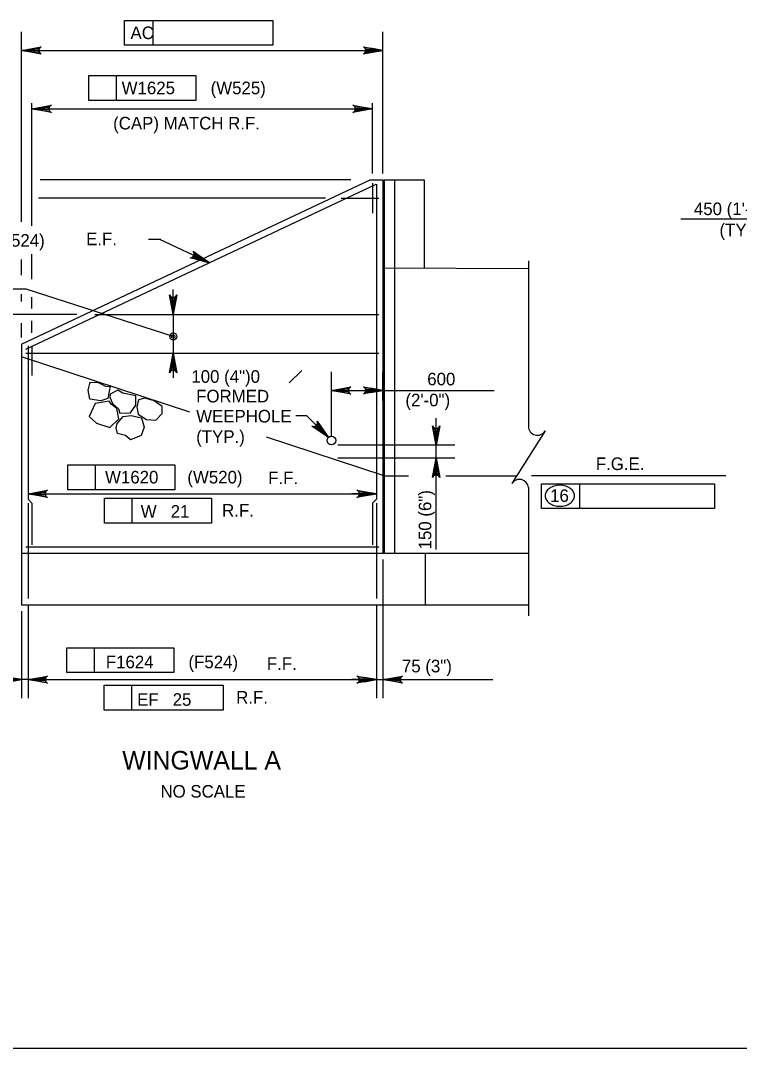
# Model space of a CAD drawing. Extents: x 638340 to 640241, y 295465 to 298435.
# Drawn here: x 638624.2 to 638795.5, y 296074.5 to 296319.4 of the extents above; entities that cross this region are included whole.
import ezdxf

# ---------------------------------------------------------------- set-up
doc = ezdxf.new("R2010")
doc.units = 0
for name, color, linetype in [('10', 7, 'Continuous'), ('2', 7, 'Continuous'), ('3', 7, 'Continuous'), ('4', 7, 'Continuous'), ('5', 7, 'Continuous'), ('6', 7, 'Continuous')]:
    doc.layers.add(name, color=color, linetype=linetype)

# ---------------------------------------------------------------- blocks, each defined once
blk = doc.blocks.new('ROCK')
at = {"layer": '4'}
for points in [[(2.36725, 1.088), (2.2065, 0.82625), (2.378625, 0.506625), (2.66975, 0.3095), (3.128875, 0.403375), (3.48475, 0.6775), (3.4915, 1.123375), (3.25625, 1.36725), (2.783625, 1.308375)], [(1.10175, -0.02725), (1.4015, -0.159125), (1.78825, -0.148875), (1.980875, -0.266), (2.343375, 0.09475), (2.27875, 0.5505), (1.969375, 0.883), (1.4225, 0.553625), (1.152875, 0.479), (1.0105, 0.082)], [(0.74675, 0.359875), (0.882, 0.16), (1.072875, -0.144), (0.892, -0.457375), (0.448125, -0.758625), (0.1, -0.49325), (-0.095, -0.146375), (0.202875, 0.1025), (0.579125, 0.219875)], [(2.231375, -0.71725), (2.2025, -0.266375), (2.45475, 0.037125), (2.9085, 0.28875), (3.2995, 0.047625), (3.46875, -0.344), (3.231625, -0.855), (2.92, -0.860375), (2.5765, -1.054625), (2.340375, -0.904375)], [(1.2085, -0.192875), (0.778375, -0.737625), (1.008375, -1.391375), (1.48725, -1.396875), (2.09825, -1.106625), (2.133375, -0.486375), (1.723125, -0.203375), (1.37425, -0.239875)]]:
    blk.add_lwpolyline(points, close=True, dxfattribs=at)

msp = doc.modelspace()

# ---------------------------------------------------------------- linework, layer by layer
at = {"layer": '10'}
for p, q in [((638624.42, 296242.32), (638707.47, 296281.44)), ((638707.47, 296281.44), (638710.54, 296281.44)), ((638710.54, 296281.44), (638710.54, 296192.49)), ((638710.8, 296281.44), (638720.35, 296281.44)), ((638710.8, 296281.44), (638710.8, 296192.49)), ((638713.27, 296281.44), (638713.27, 296192.49)), ((638720.35, 296281.44), (638720.35, 296260.47)), ((638710.8, 296260.51), (638745.21, 296260.36)), ((638624.42, 296242.32), (638624.42, 296180.18)), ((638664.51, 296226.11), (638624.42, 296239.24)), ((638710.8, 296210.94), (638682.76, 296220.13)), ((638710.8, 296210.94), (638716.64, 296210.94)), ((638725.5, 296210.94), (638742.46, 296210.94)), ((638624.42, 296192.49), (638745.21, 296192.49)), ((638720.6, 296192.49), (638720.6, 296180.18)), ((638624.42, 296180.18), (638745.21, 296180.18))]:
    msp.add_line(p, q, dxfattribs=at)
at = {"layer": '2'}
msp.add_line((639261.46, 296074.46), (638475.46, 296074.46), dxfattribs=at)
at = {"layer": '3'}
for p, q in [((638815.71, 296272.08), (638781.51, 296272.08)), ((638745.21, 296262.18), (638745.21, 296222.71)), ((638625.48, 296255.4), (638588.19, 296255.4)), ((638660.55, 296244.13), (638625.48, 296255.4)), ((638749.19, 296221.64), (638741.29, 296209.07)), ((638745.21, 296208.14), (638745.21, 296177.56))]:
    msp.add_line(p, q, dxfattribs=at)
for radius in [0.833, 0.417]:
    msp.add_circle((638660.55, 296244.13), radius, dxfattribs=at)
for centre, start, end in [((638747.34, 296222.71), 180, 330), ((638743.09, 296207.94), 5.3286, 147.8672)]:
    msp.add_arc(centre, 2.13, start, end, dxfattribs=at)
at = {"layer": '4'}
for p, q in [((638648.96, 296319.41), (638684.26, 296319.41)), ((638648.96, 296313.51), (638648.96, 296319.41)), ((638655.8, 296313.51), (638655.8, 296319.41)), ((638684.26, 296319.41), (638684.26, 296313.51)), ((638624.42, 296271.46), (638624.42, 296316.74)), ((638710.54, 296282.98), (638710.54, 296316.74)), ((638627.37, 296312.31), (638707.59, 296312.31)), ((638684.26, 296313.51), (638648.96, 296313.51)), ((638640.43, 296306.28), (638665.97, 296306.28)), ((638640.43, 296300.38), (638640.43, 296306.28)), ((638647.03, 296300.38), (638647.03, 296306.28)), ((638665.97, 296306.28), (638665.97, 296300.38)), ((638626.85, 296270.51), (638626.85, 296299.7)), ((638665.97, 296300.38), (638640.43, 296300.38)), ((638708.02, 296282.98), (638708.02, 296299.7)), ((638626.85, 296298.39), (638708.02, 296298.39)), ((638702.87, 296281.44), (638628.84, 296281.44)), ((638696.87, 296277.07), (638628.45, 296277.07)), ((638657.58, 296267.21), (638654.63, 296267.21)), ((638669.16, 296261.69), (638657.39, 296267.21)), ((638624.42, 296258.7), (638624.42, 296262.48)), ((638626.85, 296257.75), (638626.85, 296263.74)), ((638660.55, 296252.34), (638660.55, 296255.3)), ((638624.42, 296252.49), (638624.42, 296254.18)), ((638626.85, 296250.79), (638626.85, 296253.5)), ((638637.55, 296249.39), (638621.53, 296249.39)), ((638626.85, 296244.99), (638626.85, 296247.89)), ((638660.55, 296249.39), (638660.55, 296240.16)), ((638624.42, 296243.85), (638624.42, 296247.27)), ((638660.55, 296237.21), (638660.55, 296234.26)), ((638688.2, 296233.05), (638691.19, 296236.04)), ((638698.24, 296220.34), (638698.24, 296235.72)), ((638710.54, 296228.75), (638710.54, 296235.72)), ((638701.19, 296231.29), (638737.05, 296231.29)), ((638692.39, 296225.25), (638689.75, 296225.25)), ((638697.52, 296220.05), (638692.39, 296225.25)), ((638723.22, 296193.38), (638723.22, 296224.68)), ((638699.78, 296218.29), (638727.65, 296218.29)), ((638635.42, 296213.52), (638660.96, 296213.52)), ((638635.42, 296207.61), (638635.42, 296213.52)), ((638642.02, 296207.61), (638642.02, 296213.52)), ((638660.96, 296213.52), (638660.96, 296207.61)), ((638699.78, 296215.21), (638727.65, 296215.21)), ((638792.29, 296210.94), (638745.96, 296210.94)), ((638748.33, 296209.01), (638789.54, 296209.01)), ((638748.33, 296203.1), (638748.33, 296209.01)), ((638757.5, 296203.1), (638757.5, 296209.01)), ((638789.54, 296209.01), (638789.54, 296203.1)), ((638625.96, 296206.65), (638709.01, 296206.65)), ((638631.37, 296206.65), (638634.33, 296206.65)), ((638660.96, 296207.61), (638635.42, 296207.61)), ((638706.05, 296206.65), (638703.1, 296206.65)), ((638644.16, 296205.58), (638669.7, 296205.58)), ((638644.16, 296199.67), (638644.16, 296205.58)), ((638650.75, 296199.67), (638650.75, 296205.58)), ((638669.7, 296205.58), (638669.7, 296199.67)), ((638789.54, 296203.1), (638748.33, 296203.1)), ((638669.7, 296199.67), (638644.16, 296199.67)), ((638710.54, 296190.95), (638710.54, 296157.91)), ((638625.96, 296180.18), (638625.96, 296157.91)), ((638709.01, 296180.18), (638709.01, 296157.91)), ((638624.42, 296178.65), (638624.42, 296157.91)), ((638635.16, 296169.93), (638660.7, 296169.93)), ((638635.16, 296164.03), (638635.16, 296169.93)), ((638641.76, 296164.03), (638641.76, 296169.93)), ((638660.7, 296169.93), (638660.7, 296164.03)), ((638625.96, 296162.34), (638624.42, 296162.34)), ((638628.91, 296162.34), (638706.05, 296162.34)), ((638631.58, 296162.34), (638634.53, 296162.34)), ((638660.7, 296164.03), (638635.16, 296164.03)), ((638706.05, 296162.34), (638703.1, 296162.34)), ((638709.01, 296162.34), (638710.54, 296162.34)), ((638713.5, 296162.34), (638716.45, 296162.34)), ((638716.45, 296162.34), (638736.72, 296162.34)), ((638644.06, 296160.99), (638672.48, 296160.99)), ((638644.06, 296155.09), (638644.06, 296160.99)), ((638650.65, 296155.09), (638650.65, 296160.99)), ((638672.48, 296160.99), (638672.48, 296155.09)), ((638672.48, 296155.09), (638644.06, 296155.09))]:
    msp.add_line(p, q, dxfattribs=at)
for points in [[(638624.42, 296312.31), (638629.08, 296313.19), (638628.72, 296312.94), (638628.54, 296312.63), (638628.48, 296312.31), (638628.54, 296312), (638628.72, 296311.69), (638629.08, 296311.44), (638624.42, 296312.31), (638628.72, 296311.69), (638628.54, 296312), (638624.42, 296312.31), (638628.48, 296312.31), (638628.54, 296312.63), (638624.42, 296312.31), (638628.72, 296312.94)], [(638710.54, 296312.31), (638705.88, 296311.44), (638706.24, 296311.69), (638706.43, 296312), (638706.48, 296312.31), (638706.43, 296312.63), (638706.24, 296312.94), (638705.88, 296313.19), (638710.54, 296312.31), (638706.24, 296312.94), (638706.43, 296312.63), (638710.54, 296312.31), (638706.48, 296312.31), (638706.43, 296312), (638710.54, 296312.31), (638706.24, 296311.69)], [(638626.85, 296298.39), (638631.51, 296299.26), (638631.16, 296299.02), (638630.97, 296298.7), (638630.92, 296298.39), (638630.97, 296298.08), (638631.16, 296297.77), (638631.51, 296297.52), (638626.85, 296298.39), (638631.16, 296297.77), (638630.97, 296298.08), (638626.85, 296298.39), (638630.92, 296298.39), (638630.97, 296298.7), (638626.85, 296298.39), (638631.16, 296299.02)], [(638708.02, 296298.39), (638703.36, 296297.52), (638703.72, 296297.77), (638703.91, 296298.08), (638703.96, 296298.39), (638703.91, 296298.7), (638703.72, 296299.02), (638703.36, 296299.26), (638708.02, 296298.39), (638703.72, 296299.02), (638703.91, 296298.7), (638708.02, 296298.39), (638703.96, 296298.39), (638703.91, 296298.08), (638708.02, 296298.39), (638703.72, 296297.77)], [(638669.16, 296261.69), (638664.57, 296262.88), (638665, 296262.95), (638665.3, 296263.16), (638665.48, 296263.42), (638665.57, 296263.72), (638665.53, 296264.09), (638665.31, 296264.46), (638669.16, 296261.69), (638665.53, 296264.09), (638665.57, 296263.72), (638669.16, 296261.69), (638665.48, 296263.42), (638665.3, 296263.16), (638669.16, 296261.69), (638665, 296262.95)], [(638660.55, 296249.39), (638659.67, 296254.05), (638659.92, 296253.69), (638660.23, 296253.51), (638660.55, 296253.45), (638660.86, 296253.51), (638661.17, 296253.69), (638661.42, 296254.05), (638660.55, 296249.39), (638661.17, 296253.69), (638660.86, 296253.51), (638660.55, 296249.39), (638660.55, 296253.45), (638660.23, 296253.51), (638660.55, 296249.39), (638659.92, 296253.69)], [(638660.55, 296240.16), (638661.42, 296235.5), (638661.17, 296235.86), (638660.86, 296236.05), (638660.55, 296236.1), (638660.23, 296236.05), (638659.92, 296235.86), (638659.67, 296235.5), (638660.55, 296240.16), (638659.92, 296235.86), (638660.23, 296236.05), (638660.55, 296240.16), (638660.55, 296236.1), (638660.86, 296236.05), (638660.55, 296240.16), (638661.17, 296235.86)], [(638698.24, 296231.26), (638702.9, 296232.14), (638702.54, 296231.89), (638702.36, 296231.57), (638702.3, 296231.26), (638702.36, 296230.95), (638702.54, 296230.64), (638702.9, 296230.39), (638698.24, 296231.26), (638702.54, 296230.64), (638702.36, 296230.95), (638698.24, 296231.26), (638702.3, 296231.26), (638702.36, 296231.57), (638698.24, 296231.26), (638702.54, 296231.89)], [(638710.54, 296231.29), (638705.88, 296230.42), (638706.24, 296230.66), (638706.43, 296230.98), (638706.48, 296231.29), (638706.43, 296231.6), (638706.24, 296231.91), (638705.88, 296232.16), (638710.54, 296231.29), (638706.24, 296231.91), (638706.43, 296231.6), (638710.54, 296231.29), (638706.48, 296231.29), (638706.43, 296230.98), (638710.54, 296231.29), (638706.24, 296230.66)], [(638697.52, 296220.05), (638693.62, 296222.75), (638694.06, 296222.67), (638694.41, 296222.76), (638694.67, 296222.94), (638694.85, 296223.2), (638694.95, 296223.55), (638694.87, 296223.98), (638697.52, 296220.05), (638694.95, 296223.55), (638694.85, 296223.2), (638697.52, 296220.05), (638694.67, 296222.94), (638694.41, 296222.76), (638697.52, 296220.05), (638694.06, 296222.67)], [(638723.22, 296218.17), (638722.35, 296222.83), (638722.6, 296222.47), (638722.91, 296222.29), (638723.22, 296222.23), (638723.54, 296222.29), (638723.85, 296222.47), (638724.1, 296222.83), (638723.22, 296218.17), (638723.85, 296222.47), (638723.54, 296222.29), (638723.22, 296218.17), (638723.22, 296222.23), (638722.91, 296222.29), (638723.22, 296218.17), (638722.6, 296222.47)], [(638723.22, 296215.21), (638724.1, 296210.54), (638723.85, 296210.9), (638723.54, 296211.09), (638723.22, 296211.14), (638722.91, 296211.09), (638722.6, 296210.9), (638722.35, 296210.54), (638723.22, 296215.21), (638722.6, 296210.9), (638722.91, 296211.09), (638723.22, 296215.21), (638723.22, 296211.14), (638723.54, 296211.09), (638723.22, 296215.21), (638723.85, 296210.9)], [(638625.96, 296206.65), (638630.62, 296207.52), (638630.26, 296207.27), (638630.07, 296206.96), (638630.02, 296206.65), (638630.07, 296206.34), (638630.26, 296206.02), (638630.62, 296205.78), (638625.96, 296206.65), (638630.26, 296206.02), (638630.07, 296206.34), (638625.96, 296206.65), (638630.02, 296206.65), (638630.07, 296206.96), (638625.96, 296206.65), (638630.26, 296207.27)], [(638709.01, 296206.65), (638704.35, 296205.78), (638704.7, 296206.02), (638704.89, 296206.34), (638704.94, 296206.65), (638704.89, 296206.96), (638704.7, 296207.27), (638704.35, 296207.52), (638709.01, 296206.65), (638704.7, 296207.27), (638704.89, 296206.96), (638709.01, 296206.65), (638704.94, 296206.65), (638704.89, 296206.34), (638709.01, 296206.65), (638704.7, 296206.02)], [(638624.42, 296162.34), (638619.76, 296161.47), (638620.12, 296161.71), (638620.3, 296162.03), (638620.36, 296162.34), (638620.3, 296162.65), (638620.12, 296162.96), (638619.76, 296163.21), (638624.42, 296162.34), (638620.12, 296162.96), (638620.3, 296162.65), (638624.42, 296162.34), (638620.36, 296162.34), (638620.3, 296162.03), (638624.42, 296162.34), (638620.12, 296161.71)], [(638625.96, 296162.34), (638630.62, 296163.21), (638630.26, 296162.96), (638630.07, 296162.65), (638630.02, 296162.34), (638630.07, 296162.03), (638630.26, 296161.71), (638630.62, 296161.47), (638625.96, 296162.34), (638630.26, 296161.71), (638630.07, 296162.03), (638625.96, 296162.34), (638630.02, 296162.34), (638630.07, 296162.65), (638625.96, 296162.34), (638630.26, 296162.96)], [(638709.01, 296162.34), (638704.35, 296161.47), (638704.7, 296161.71), (638704.89, 296162.03), (638704.94, 296162.34), (638704.89, 296162.65), (638704.7, 296162.96), (638704.35, 296163.21), (638709.01, 296162.34), (638704.7, 296162.96), (638704.89, 296162.65), (638709.01, 296162.34), (638704.94, 296162.34), (638704.89, 296162.03), (638709.01, 296162.34), (638704.7, 296161.71)], [(638710.54, 296162.34), (638715.2, 296163.21), (638714.85, 296162.96), (638714.66, 296162.65), (638714.61, 296162.34), (638714.66, 296162.03), (638714.85, 296161.71), (638715.2, 296161.47), (638710.54, 296162.34), (638714.85, 296161.71), (638714.66, 296162.03), (638710.54, 296162.34), (638714.61, 296162.34), (638714.66, 296162.65), (638710.54, 296162.34), (638714.85, 296162.96)]]:
    msp.add_lwpolyline(points, dxfattribs=at)
for points in [[(638627.37, 296312.81), (638627.37, 296311.82), (638624.42, 296312.31)], [(638707.59, 296312.81), (638707.59, 296311.82), (638710.54, 296312.31)], [(638666.69, 296263.39), (638666.28, 296262.5), (638669.16, 296261.69)], [(638660.05, 296252.34), (638661.04, 296252.34), (638660.55, 296249.39)], [(638660.05, 296237.21), (638661.04, 296237.21), (638660.55, 296240.16)], [(638701.19, 296231.78), (638701.19, 296230.8), (638698.24, 296231.29)], [(638707.59, 296231.78), (638707.59, 296230.8), (638710.54, 296231.29)], [(638722.73, 296221.12), (638723.72, 296221.12), (638723.22, 296218.17)], [(638722.73, 296211.99), (638723.72, 296211.99), (638723.22, 296214.94)], [(638628.91, 296207.14), (638628.91, 296206.16), (638625.96, 296206.65)], [(638706.05, 296207.14), (638706.05, 296206.16), (638709.01, 296206.65)], [(638621.47, 296162.83), (638621.47, 296161.84), (638624.42, 296162.34)], [(638628.91, 296162.83), (638628.91, 296161.84), (638625.96, 296162.34)], [(638706.05, 296162.83), (638706.05, 296161.84), (638709.01, 296162.34)], [(638713.5, 296162.83), (638713.5, 296161.84), (638710.54, 296162.34)]]:
    msp.add_lwpolyline(points, close=True, dxfattribs=at)
msp.add_circle((638698.24, 296219.32), 1.03, dxfattribs=at)
for centre, radius, start, end in [((638752.36, 296204.96), 3.66, 106.5358, 125.6316), ((638752.71, 296203.8), 4.87, 90, 106.5358), ((638752.71, 296203.8), 4.87, 73.4642, 90), ((638753.05, 296204.96), 3.66, 54.3684, 73.4642), ((638751.03, 296206.16), 1.83, 149.9767, 180), ((638751.03, 296206.16), 1.83, 180, 210.0233), ((638751.83, 296205.7), 2.76, 125.6316, 149.9767), ((638753.58, 296205.7), 2.76, 30.0233, 54.3684), ((638754.38, 296206.16), 1.83, 0, 30.0233), ((638754.38, 296206.16), 1.83, 329.9767, 0), ((638751.83, 296206.63), 2.76, 210.0233, 234.3684), ((638752.36, 296207.36), 3.66, 234.3684, 253.4642), ((638752.71, 296208.52), 4.87, 253.4642, 270), ((638752.71, 296208.52), 4.87, 270, 286.5358), ((638753.05, 296207.36), 3.66, 286.5358, 305.6316), ((638753.58, 296206.63), 2.76, 305.6316, 329.9767)]:
    msp.add_arc(centre, radius, start, end, dxfattribs=at)
at = {"layer": '5'}
for p, q in [((638708.02, 296280.65), (638708.03, 296273.55)), ((638626.85, 296241.91), (638626.85, 296234.81))]:
    msp.add_line(p, q, dxfattribs=at)
at = {"layer": '6'}
for p, q in [((638625.44, 296241.1), (638708.9, 296280.42)), ((638709.01, 296280.42), (638709.01, 296205.36)), ((638700.6, 296277.07), (638709.52, 296277.07)), ((638641.84, 296249.39), (638709.52, 296249.39)), ((638625.96, 296241.91), (638625.96, 296205.36)), ((638625.44, 296240.16), (638709.52, 296240.16)), ((638625.96, 296205.36), (638626.89, 296204.43)), ((638625.96, 296204.43), (638625.96, 296181.72)), ((638626.89, 296204.43), (638626.89, 296194.48)), ((638709.01, 296205.36), (638708.07, 296204.43)), ((638708.07, 296204.43), (638708.07, 296194.48)), ((638709.01, 296204.43), (638709.01, 296181.72)), ((638625.44, 296194.03), (638709.52, 296194.03))]:
    msp.add_line(p, q, dxfattribs=at)

# ---------------------------------------------------------------- block references
at = {"layer": '4', "xscale": 4.921475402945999, "yscale": 4.921475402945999, "rotation": -43.131989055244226}
msp.add_blockref('ROCK', (638641.6, 296233.45), dxfattribs=at)

# ---------------------------------------------------------------- texts
at = {"layer": '3'}
for s, height, p in [('450 (1\'-6")', 3.0001, (638784.65, 296273.04)), ('(TYP.)', 3, (638790.75, 296268.03)), ('100 (4")0', 3, (638664.87, 296233.09))]:
    msp.add_text(s, height=height, dxfattribs=at).set_placement(p)
at = {"layer": '4'}
for s, height, p in [('AC', 3, (638650.37, 296314.99)), ('W1625', 3, (638648.26, 296301.86)), ('(W525)', 3, (638669.47, 296301.86)), ('(CAP) MATCH R.F.', 3.0001, (638646.23, 296293.46)), ('(W524)', 3, (638616.77, 296265.52)), ('E.F.', 3, (638639.79, 296265.88)), ('600', 3, (638721.1, 296232.48)), ('FORMED', 3, (638666.02, 296228.41)), ('(2\'-0")', 3, (638715.89, 296227.48)), ('WEEPHOLE', 3, (638666.02, 296223.63)), ('(TYP.)', 3, (638666.02, 296218.76)), ('F.G.E.', 3, (638761.27, 296212.29)), ('W1620', 3, (638644.3, 296209.1)), ('(W520)', 3, (638663.92, 296209.1)), ('F.F.', 3, (638683.18, 296208.93)), ('16', 3, (638750.38, 296204.7)), ('W   21', 3, (638652.81, 296200.93)), ('R.F.', 3, (638672.2, 296201.19)), ('F1624', 3, (638644.49, 296165.06)), ('(F524)', 3, (638664.19, 296165.06)), ('F.F.', 3, (638682.86, 296164.67)), ('75 (3")', 3, (638715.06, 296164.08)), ('R.F.', 3, (638675.56, 296156.62)), ('EF   25', 3, (638651.95, 296156.12)), ('WINGWALL A', 4.429, (638648.39, 296140.93)), ('NO SCALE', 3, (638657.51, 296134.23))]:
    msp.add_text(s, height=height, dxfattribs=at).set_placement(p)
msp.add_text('150 (6")', height=3, rotation=90, dxfattribs=at).set_placement((638722.06, 296193.38))

doc.saveas('drawing.dxf')
